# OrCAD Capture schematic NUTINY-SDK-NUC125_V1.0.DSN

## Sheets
1 Nu-Link: size A4; title: NuLink-Me; rev: 3.0; note: 1
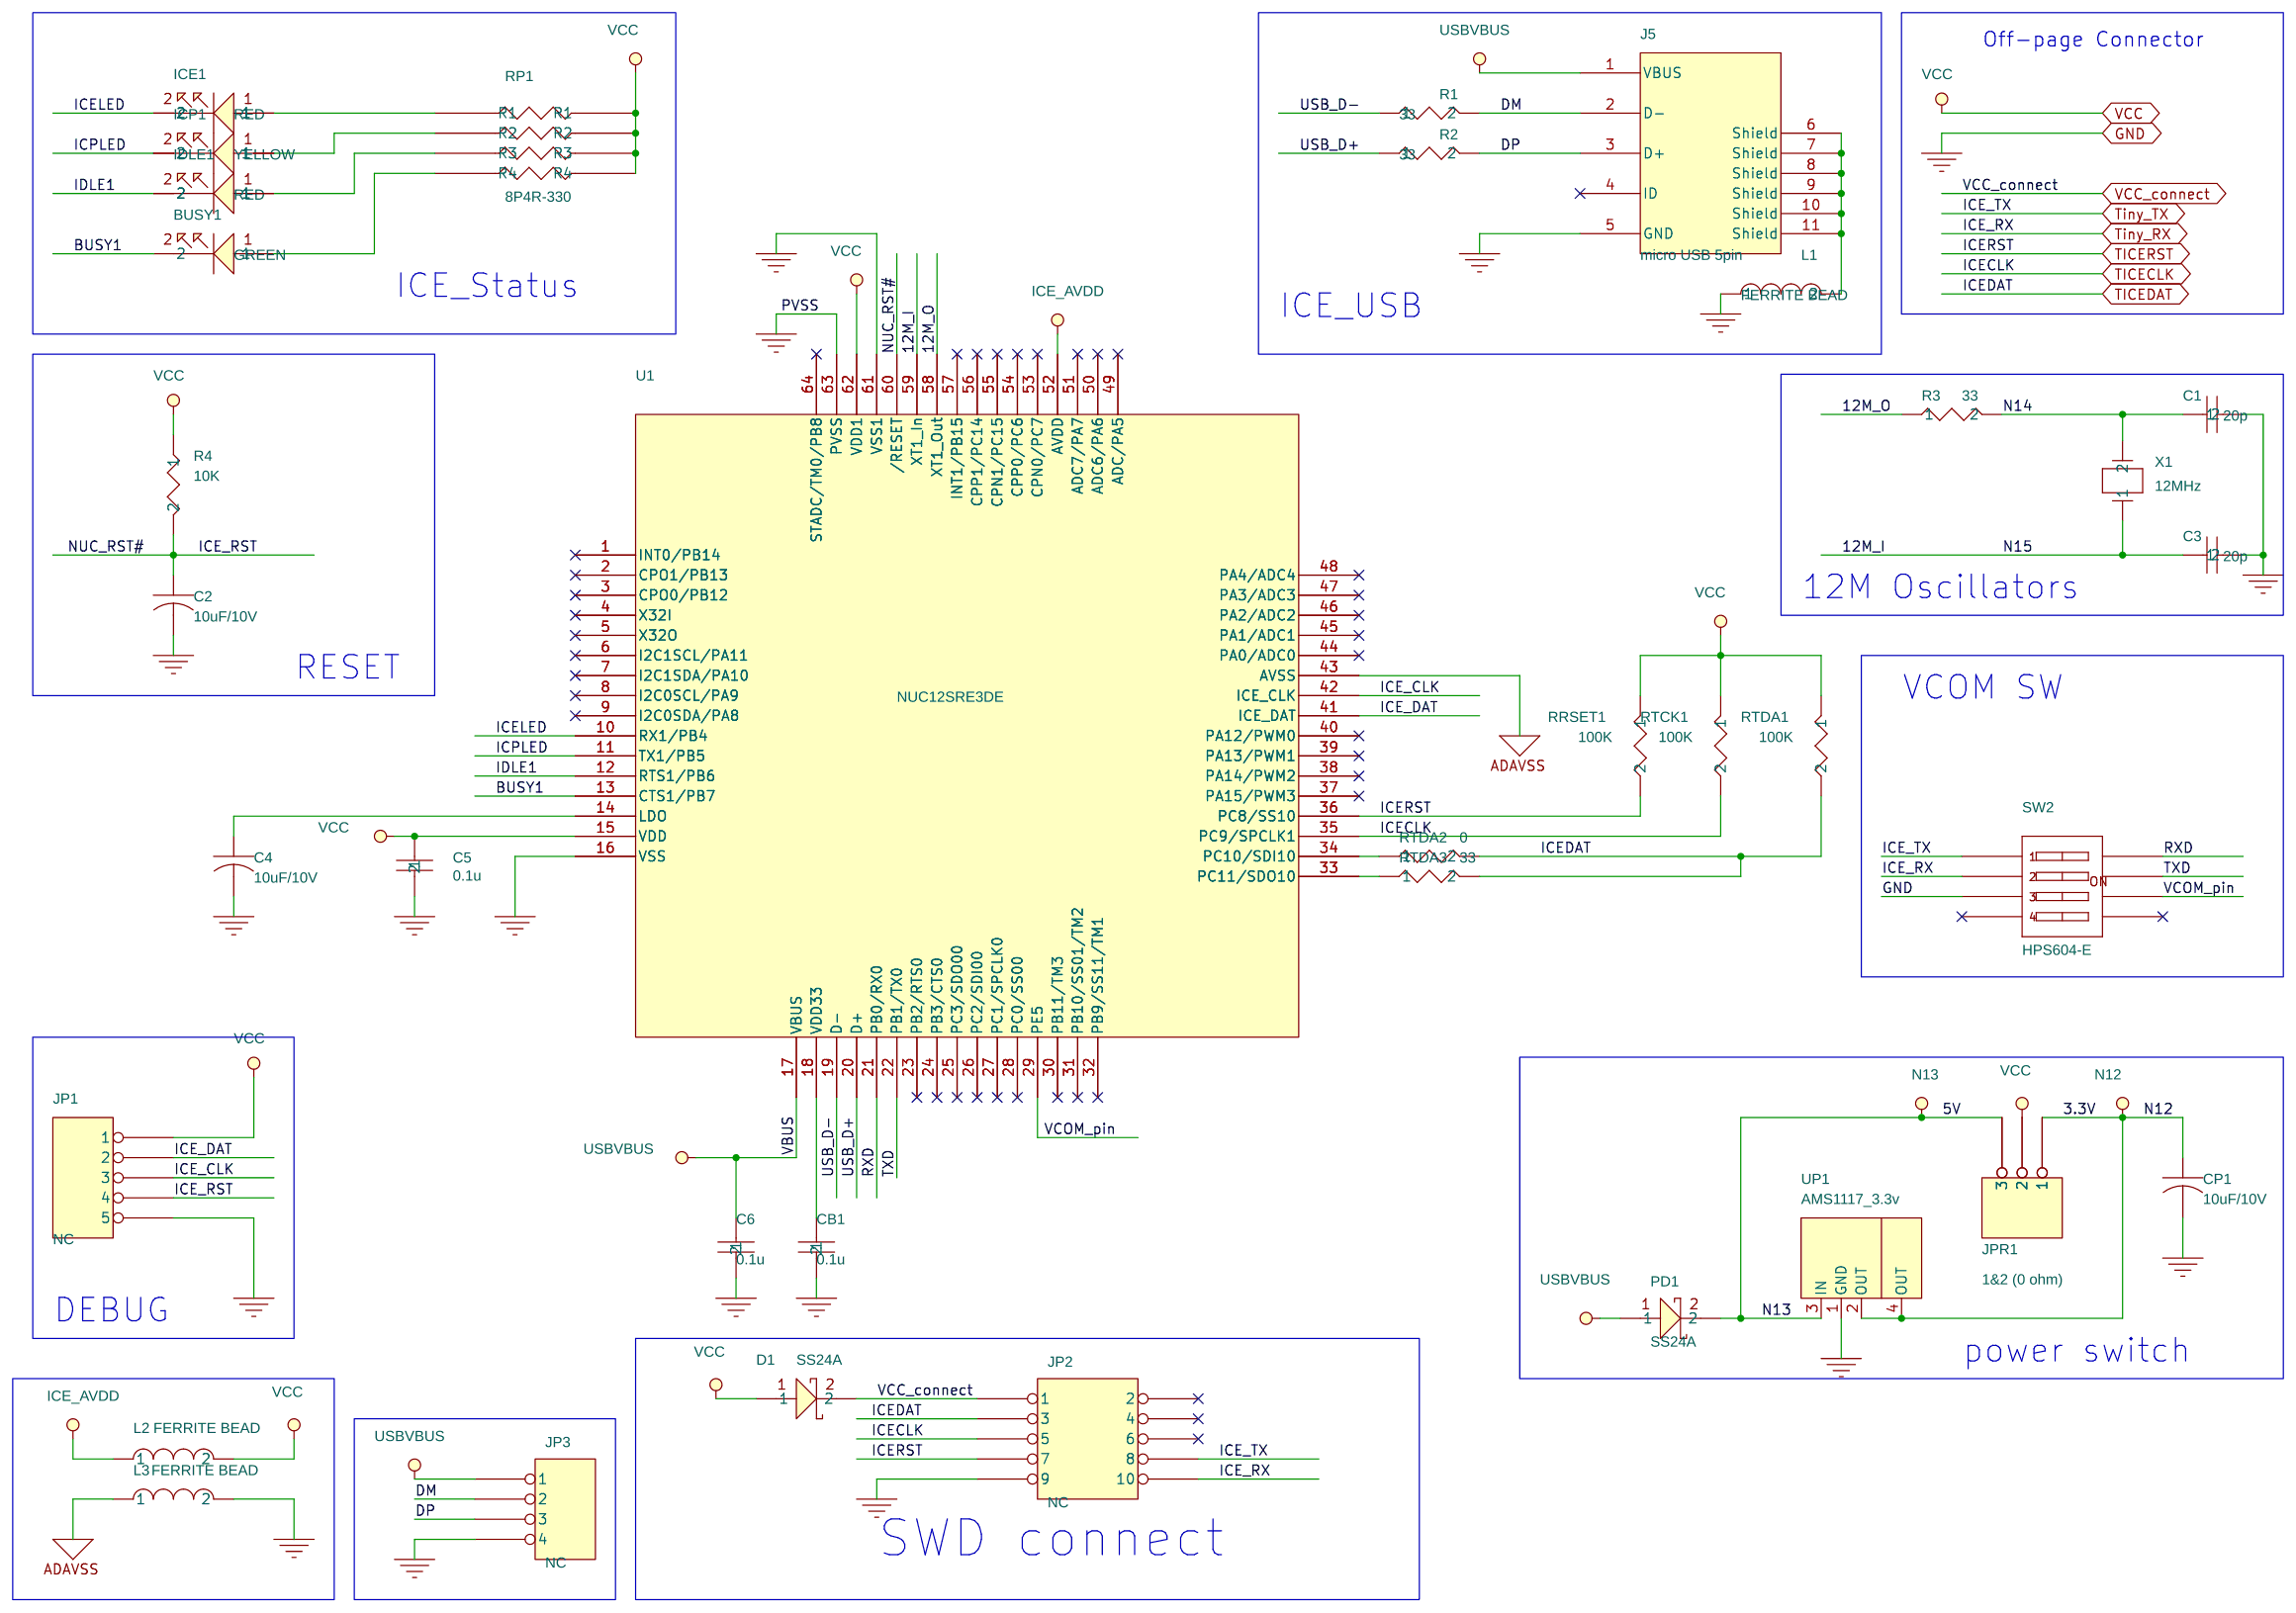
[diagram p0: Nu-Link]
2 SDK_Circuit: size A4; title: SDK Circuit; rev: 1.0; note: 2
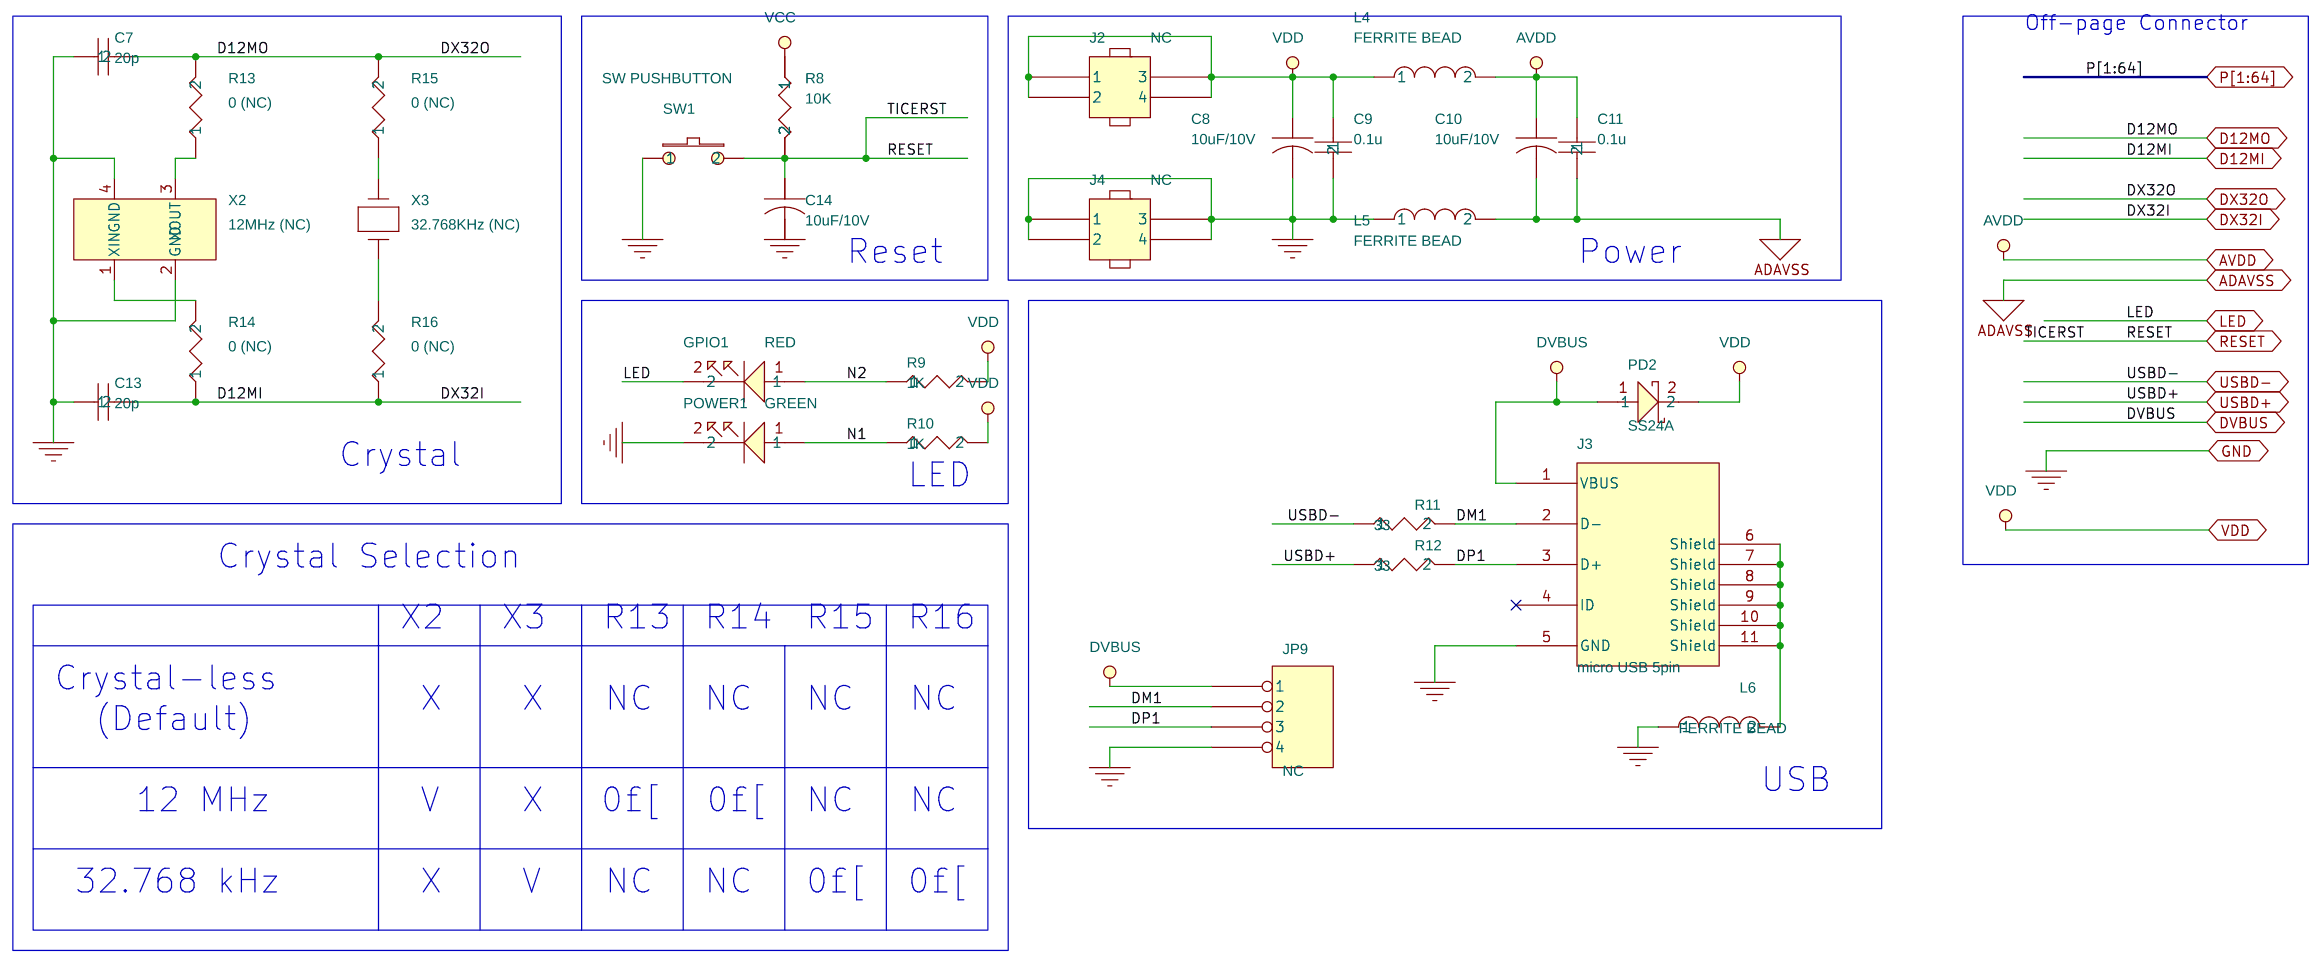
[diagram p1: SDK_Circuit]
3 Target Chip: size A4; title: NuTiny-SDK-NUC125; rev: 1.0
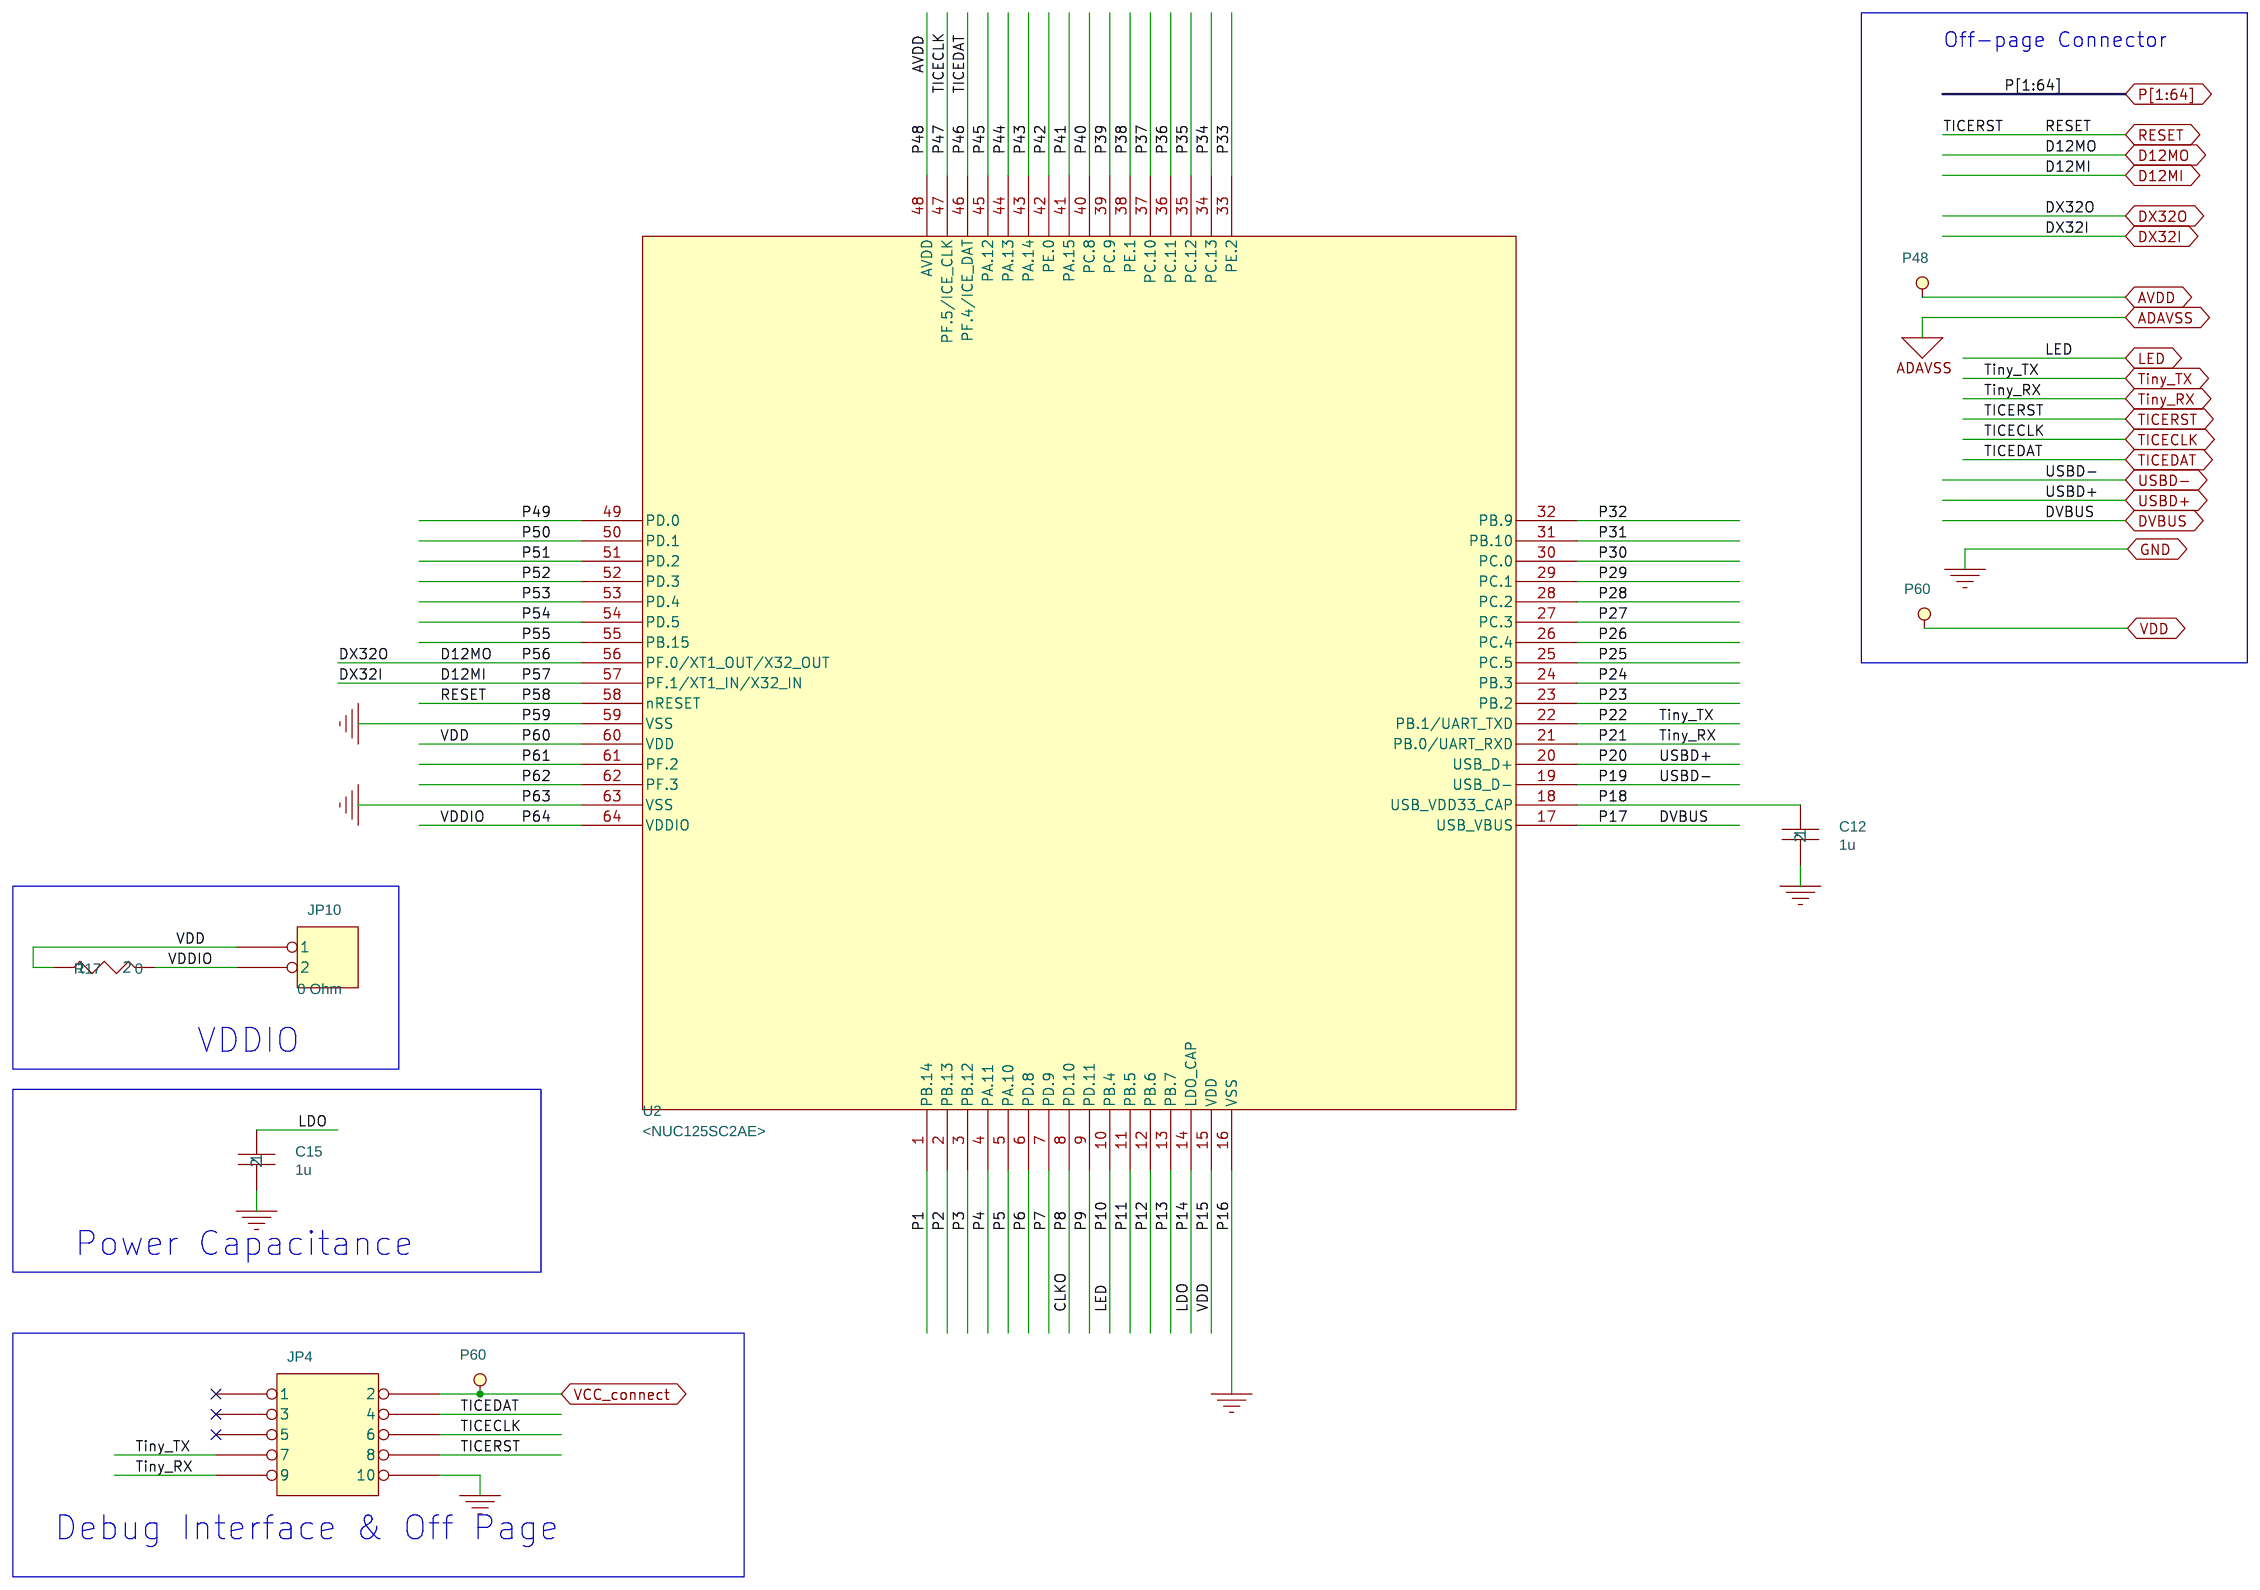
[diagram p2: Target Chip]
4 B-GPIO for 64 pin: size A4; title: GPIO for 64 pin; rev: 1.0
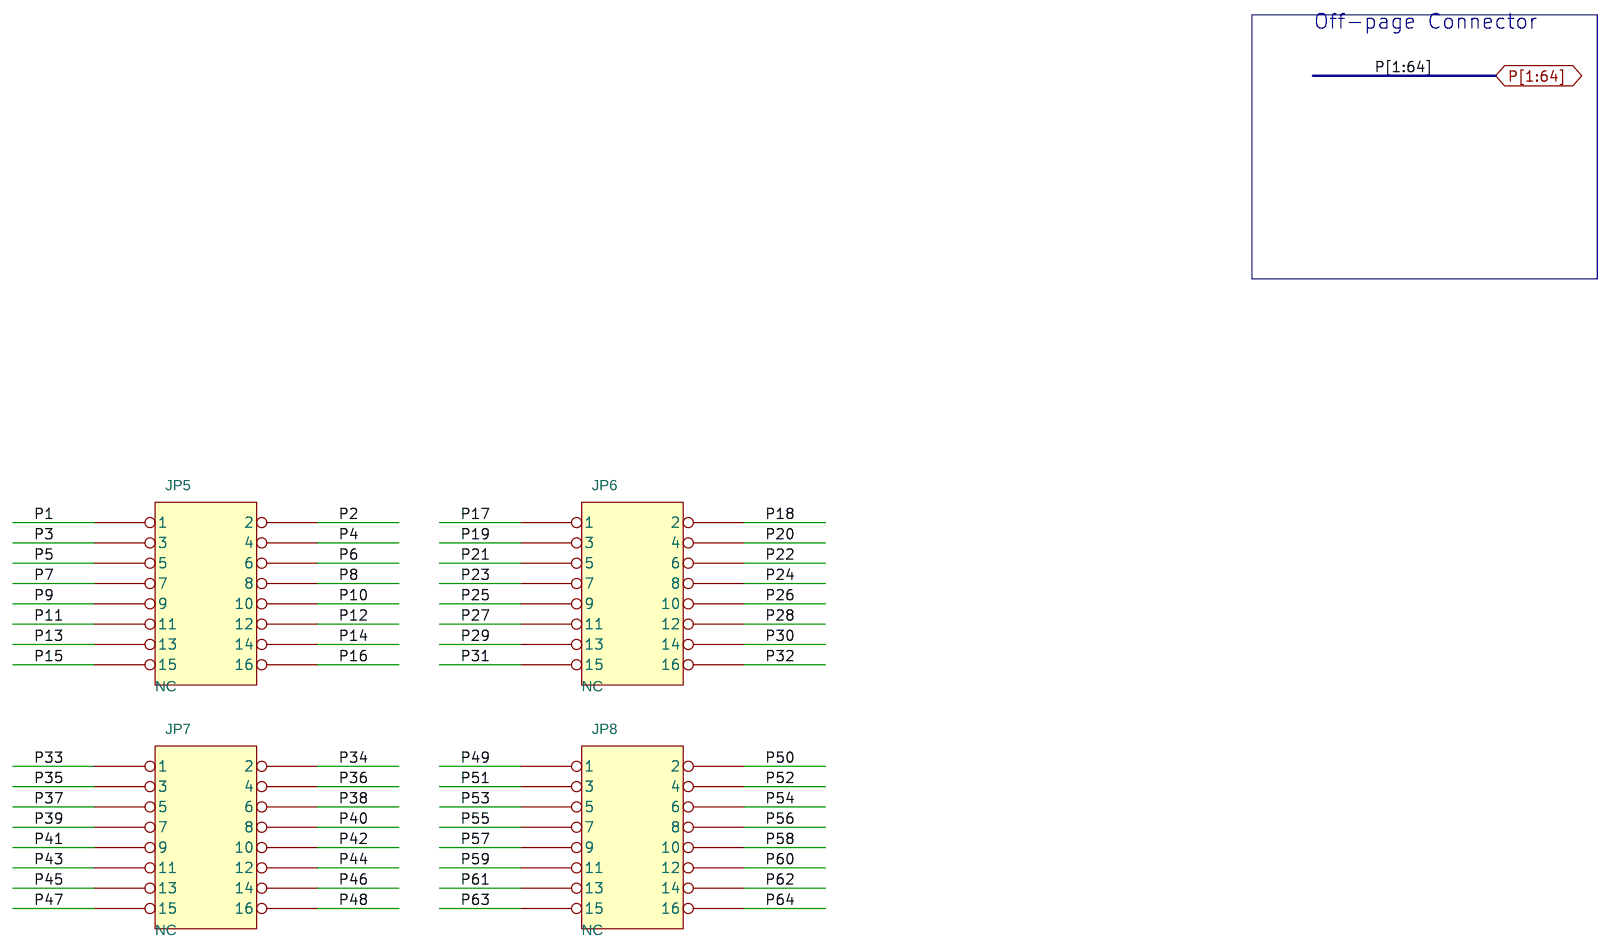
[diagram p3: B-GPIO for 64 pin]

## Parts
sheet B-GPIO for 64 pin
JP5  NC  [HEADER8X2]
JP6  NC  [HEADER8X2]
JP7  NC  [HEADER8X2]
JP8  NC  [HEADER8X2]
sheet Nu-Link
BUSY1  GREEN  [LED0805]
C1  20p  [C0603]
C2  10uF/10V  [TANT-A]
C3  20p  [C0603]
C4  10uF/10V  [TANT-A]
C5  0.1u  [C0603]
C6  0.1u  [C0603]
CB1  0.1u  [C0603]
CP1  10uF/10V  [TANT-A]
D1  SS24A  [RB060L]
ICE1  RED  [LED0805]
ICP1  YELLOW  [LED0805]
IDLE1  RED  [LED0805]
J5  micro USB 5pin  [MICRO_USB_AB]
JP1  NC  [HEADER1X5]
JP2  NC  [HEADER5X2]
JP3  NC  [HEADER1X4]
JPR1  1&2 (0 ohm)  [R0603X2]
L1  FERRITE BEAD  [L0603]
L2  FERRITE BEAD  [L0603]
L3  FERRITE BEAD  [L0603]
PD1  SS24A  [RB060L]
R1  33  [R0603]
R2  33  [R0603]
R3  33  [R0603]
R4  10K  [R0603]
RP1  8P4R-330  [8P4RA]
RRSET1  100K  [R0603]
RTCK1  100K  [R0603]
RTDA1  100K  [R0603]
RTDA2  0  [R0603]
RTDA3  33  [R0603]
SW2  HPS604-E  [SW1X4]
U1  NUC12SRE3DE  [NCU120_LQFP_64]
UP1  AMS1117_3.3v  [SOT-223-1]
X1  12MHz  [XTAL\LP\SMD]
sheet SDK_Circuit
C7  20p  [C0603]
C8  10uF/10V  [TANT-A]
C9  0.1u  [C0603]
C10  10uF/10V  [TANT-A]
C11  0.1u  [C0603]
C13  20p  [C0603]
C14  10uF/10V  [TANT-A]
GPIO1  RED  [LED0805]
J2  NC  [header2x2]
J3  micro USB 5pin  [MICRO_USB_AB]
J4  NC  [header2x2]
JP9  NC  [HEADER1X4]
L4  FERRITE BEAD  [L0603]
L5  FERRITE BEAD  [L0603]
L6  FERRITE BEAD  [L0603]
PD2  SS24A  [RB060L]
POWER1  GREEN  [LED0805]
R8  10K  [R0603]
R9  1K  [R0603]
R10  1K  [R0603]
R11  33  [R0603]
R12  33  [R0603]
R13  0 (NC)  [R0603]
R14  0 (NC)  [R0603]
R15  0 (NC)  [R0603]
R16  0 (NC)  [R0603]
SW1  SW PUSHBUTTON  [SW-2P-SMD]
X2  12MHz (NC)  [XTAL4P_SMD]
X3  32.768KHz (NC)  [9HT9]
sheet Target Chip
C12  1u  [C0603]
C15  1u  [C0603]
JP4  NC  [HEADER5X2]
JP10  0 Ohm  [sip-2p]
R17  0  [R0603]
U2  NUC121SC1AE  [LQFP64_7X7]

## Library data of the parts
JP5 = HEADER_8X2_3
JP6 = HEADER_8X2
JP7 = HEADER_8X2_1
JP8 = HEADER_8X2_2
BUSY1 POWER1 = LED_GREEN
C1 C7 = C_20p
C2 C4 C8 C10 C14 CP1 = C_10uF_10V
C3 C13 = C_20p_1
C5 C11 = C_0.1u
C6 C9 = C_0.1u_1
CB1 = C_0.1u_2
D1 = D_SS24A_v2_1
GPIO1 ICE1 = LED_RED
ICP1 = LED_YELLOW
IDLE1 = LED_RED_1
J3 J5 = micro_USB_5pin_0
JP1 = HEADER_5
JP2 JP4 = HEADER_5X2
JP3 JP9 = HEADER_4
JPR1 = HEADER_3
L1 L5 = FERRITE_BEAD_2
L2 L6 = FERRITE_BEAD
L3 L4 = FERRITE_BEAD_1
PD1 PD2 = D_SS24A_v2
R1 R11 = R_33
R2 R12 = R_33_1
R3 = R_33_3
R4 R8 = R_10K
RP1 = 8P4R-330
RRSET1 = R_100K_2
RTCK1 = R_100K_1
RTDA1 = R_100K
R13 R17 RTDA2 = R_0
RTDA3 = R_33_2
SW2 = SW_DIP-4_2
U1 = NCU120_LQFP_1
UP1 = TO-247_Regulator_10
X1 = Xtal_12MHz
J2 J4 = HEADER_2X2
R9 = R_1K
R10 = R_1K_1
R14 = R_0_1
R15 = R_0_3
R16 = R_0_2
SW1 = SW_PUSHBUTTON_0
X2 = Crystal_SMD_1
X3 = MA306_SM_0
C12 = C_1u_1
C15 = C_1u
JP10 = HEADER_3_4
U2 = NUC121SC1AE_2: NUC123SD4AN0: <NUC125SC2AE>

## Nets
3.3V: CP1.1 JPR1.1 UP1.2(OUT) UP1.4(OUT)
5V: JPR1.3 PD1.2 UP1.3(IN)
AVDD: C10.1 C11.1 JP7.16 L4.2 U2.48(AVDD)
AVSS: L3.1 U1.43(AVSS)
DVBUS: J3.1(VBUS) JP6.1 JP9.1 PD2.1 U2.17(USB_VBUS)
GND: C1.2 C2.2 C3.2 C4.2 C5.2 C6.2 C7.1 C8.2 C9.2 C12.2 C13.1 C14.2 C15.2 CB1.2 CP1.2 J3.5(GND) J4.1(3) J4.2(4) J4.3(1) J4.4(2) J5.5(GND) JP1.5 JP2.9 JP3.4 JP4.10 JP5.16 JP8.11 JP8.15 JP9.4 L1.1 L3.2 L5.1 L6.1 POWER1.2 SW1.1 SW2.3(A3) U1.16(VSS) U1.61(VSS1) U1.63(PVSS) U2.16(VSS) U2.59(VSS) U2.63(VSS) UP1.1(GND) X2.2(GND) X2.4(GND)
VCC: C5.1 D1.1 JP1.1 JPR1.2 L2.2 R4.1 RP1.2(R1) RP1.4(R2) RP1.6(R3) RP1.8(R4) RRSET1.1 RTCK1.1 RTDA1.1 U1.15(VDD) U1.62(VDD1)
12M_I: C3.1 U1.59(XT1_In) X1.1
12M_O: R3.1 U1.58(XT1_Out)
ADAVSS: C10.2 C11.2 L5.2
BUSY1: BUSY1.2 U1.13(CTS1/PB7)
D12MI: C13.2 JP8.9 R14.1 R16.1 U2.57(PF.1/XT1_IN/X32_IN)
D12MO: C7.2 JP8.8 R13.2 R15.2 U2.56(PF.0/XT1_OUT/X32_OUT)
DM: J5.2(D-) JP3.2 R1.2
DM1: J3.2(D-) JP9.2 R11.2
DP: J5.3(D+) JP3.3 R2.2
DP1: J3.3(D+) JP9.3 R12.2
ICE_AVDD: L2.1 U1.52(AVDD)
ICE_CLK: JP1.3 U1.42(ICE_CLK)
ICE_DAT: JP1.2 U1.41(ICE_DAT)
ICE_RST: C2.1 JP1.4 R4.2 U1.60(/RESET)
ICELED: ICE1.2 U1.10(RX1/PB4)
ICPLED: ICP1.2 U1.11(TX1/PB5)
IDLE1: IDLE1.2 U1.12(RTS1/PB6)
LED: GPIO1.2 JP5.10 U2.10(PB.4)
N1: POWER1.1 R10.1
N2: GPIO1.1 R9.1
N14: C1.1 R3.2 X1.2
P1: JP5.1 U2.1(PB.14)
P2: JP5.2 U2.2(PB.13)
P3: JP5.3 U2.3(PB.12)
P4: JP5.4 U2.4(PA.11)
P5: JP5.5 U2.5(PA.10)
P6: JP5.6 U2.6(PD.8)
P7: JP5.7 U2.7(PD.9)
P8: JP5.8 U2.8(PD.10)
P9: JP5.9 U2.9(PD.11)
P11: JP5.11 U2.11(PB.5)
P12: JP5.12 U2.12(PB.6)
P13: JP5.13 U2.13(PB.7)
P14: C15.1 JP5.14 U2.14(LDO_CAP)
P15: C8.1 C9.1 D1.2 J2.1(3) J2.2(4) J2.3(1) J2.4(2) JP2.1 JP4.2 JP5.15 JP8.12 JP10.1 L4.1 PD2.2 R8.1 R9.2 R10.2 R17.1 U2.15(VDD) U2.60(VDD)
P18: C12.1 JP6.2 U2.18(USB_VDD33_CAP)
P19: JP6.3 R11.1 U2.19(USB_D-)
P20: JP6.4 R12.1 U2.20(USB_D+)
P21: JP2.10 JP4.9 JP6.5 SW2.2(A2) U2.21(PB.0/UART_RXD)
P22: JP2.8 JP4.7 JP6.6 SW2.1(A1) U2.22(PB.1/UART_TXD)
P23: JP6.7 U2.23(PB.2)
P24: JP6.8 U2.24(PB.3)
P25: JP6.9 U2.25(PC.5)
P26: JP6.10 U2.26(PC.4)
P27: JP6.11 U2.27(PC.3)
P28: JP6.12 U2.28(PC.2)
P29: JP6.13 U2.29(PC.1)
P30: JP6.14 U2.30(PC.0)
P31: JP6.15 U2.31(PB.10)
P32: JP6.16 U2.32(PB.9)
P33: JP7.1 U2.33(PE.2)
P34: JP7.2 U2.34(PC.13)
P35: JP7.3 U2.35(PC.12)
P36: JP7.4 U2.36(PC.11)
P37: JP7.5 U2.37(PC.10)
P38: JP7.6 U2.38(PE.1)
P39: JP7.7 U2.39(PC.9)
P40: JP7.8 U2.40(PC.8)
P41: JP7.9 U2.41(PA.15)
P42: JP7.10 U2.42(PE.0)
P43: JP7.11 U2.43(PA.14)
P44: JP7.12 U2.44(PA.13)
P45: JP7.13 U2.45(PA.12)
P46: JP2.3 JP4.4 JP7.14 RTDA1.2 RTDA2.2 RTDA3.2 U2.46(PF.4/ICE_DAT)
P47: JP2.5 JP4.6 JP7.15 RTCK1.2 U1.35(PC9/SPCLK1) U2.47(PF.5/ICE_CLK)
P49: JP8.1 U2.49(PD.0)
P50: JP8.2 U2.50(PD.1)
P51: JP8.3 U2.51(PD.2)
P52: JP8.4 U2.52(PD.3)
P53: JP8.5 U2.53(PD.4)
P54: JP8.6 U2.54(PD.5)
P55: JP8.7 U2.55(PB.15)
P58: C14.1 JP2.7 JP4.8 JP8.10 R8.2 RRSET1.2 SW1.2 U1.36(PC8/SS10) U2.58(nRESET)
P61: JP8.13 U2.61(PF.2)
P62: JP8.14 U2.62(PF.3)
P64: JP8.16 JP10.2 R17.2 U2.64(VDDIO)
RXD: SW2.8(B1) U1.21(PB0/RX0)
TXD: SW2.7(B2) U1.22(PB1/TX0)
USB_D+: R2.1 U1.20(D+)
USB_D-: R1.1 U1.19(D-)
USBVBUS: C6.1 J5.1(VBUS) JP3.1 PD1.1 U1.17(VBUS)
VCOM_pin: SW2.6(B3) U1.29(PE5)
N00874: BUSY1.1 RP1.7(R4)
N00882: IDLE1.1 RP1.5(R3)
N16812063: C4.1 U1.14(LDO)
N16812255: CB1.1 U1.18(VDD33)
N16812376: RTDA3.1 U1.33(PC11/SDO10)
N17861502: RTDA2.1 U1.34(PC10/SDI10)
N21812882: ICE1.1 RP1.1(R1)
N21823371: ICP1.1 RP1.3(R2)
N22914175: R13.1 X2.3(XOUT)
N22914261: R16.2 X3.2
N22914263: R15.1 X3.1
N22914307: R14.2 X2.1(XIN)
N22989760: J5.6(Shield) J5.7(Shield) J5.8(Shield) J5.9(Shield) J5.10(Shield) J5.11(Shield) L1.2
N22993573: J3.6(Shield) J3.7(Shield) J3.8(Shield) J3.9(Shield) J3.10(Shield) J3.11(Shield) L6.2

Not connected (* = marked no-connect by the designer): J3 4(ID)*; J5 4(ID)*; JP2 2* 4* 6*; JP4 1* 3* 5*; SW2 4(A4)* 5(B4)*; U1 1(INT0/PB14)* 2(CPO1/PB13)* 3(CPO0/PB12)* 4(X32I)* 5(X32O)* 6(I2C1SCL/PA11)* 7(I2C1SDA/PA10)* 8(I2C0SCL/PA9)* 9(I2C0SDA/PA8)* 23(PB2/RTS0)* 24(PB3/CTS0)* 25(PC3/SDO00)* 26(PC2/SDI00)* 27(PC1/SPCLK0)* 28(PC0/SS00)* 30(PB11/TM3)* 31(PB10/SS01/TM2)* 32(PB9/SS11/TM1)* 37(PA15/PWM3)* 38(PA14/PWM2)* 39(PA13/PWM1)* 40(PA12/PWM0)* 44(PA0/ADC0)* 45(PA1/ADC1)* 46(PA2/ADC2)* 47(PA3/ADC3)* 48(PA4/ADC4)* 49(ADC/PA5)* 50(ADC6/PA6)* 51(ADC7/PA7)* 53(CPN0/PC7)* 54(CPP0/PC6)* 55(CPN1/PC15)* 56(CPP1/PC14)* 57(INT1/PB15)* 64(STADC/TM0/PB8)*

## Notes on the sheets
sheet 1
- Off-page Connector
- ICE_Status
- ICE_USB
- 12M Oscillators
- RESET
- VCOM SW
- DEBUG
- power switch
- SWD connect
sheet 2
- Off-page Connector
- Reset
- Power
- Crystal
- LED
- Crystal Selection
- X2
- X3
- R13
- R14
- R15
- R16
- Crystal-less
- X
- X
- NC
- NC
- NC
- NC
- (Default)
- USB
- 12 MHz
- V
- X
- 0£[
- 0£[
- NC
- NC
- 32.768 kHz
- X
- V
- NC
- NC
- 0£[
- 0£[
sheet 3
- Off-page Connector
- VDDIO
- Power Capacitance
- Debug Interface & Off Page
sheet 4
- Off-page Connector
